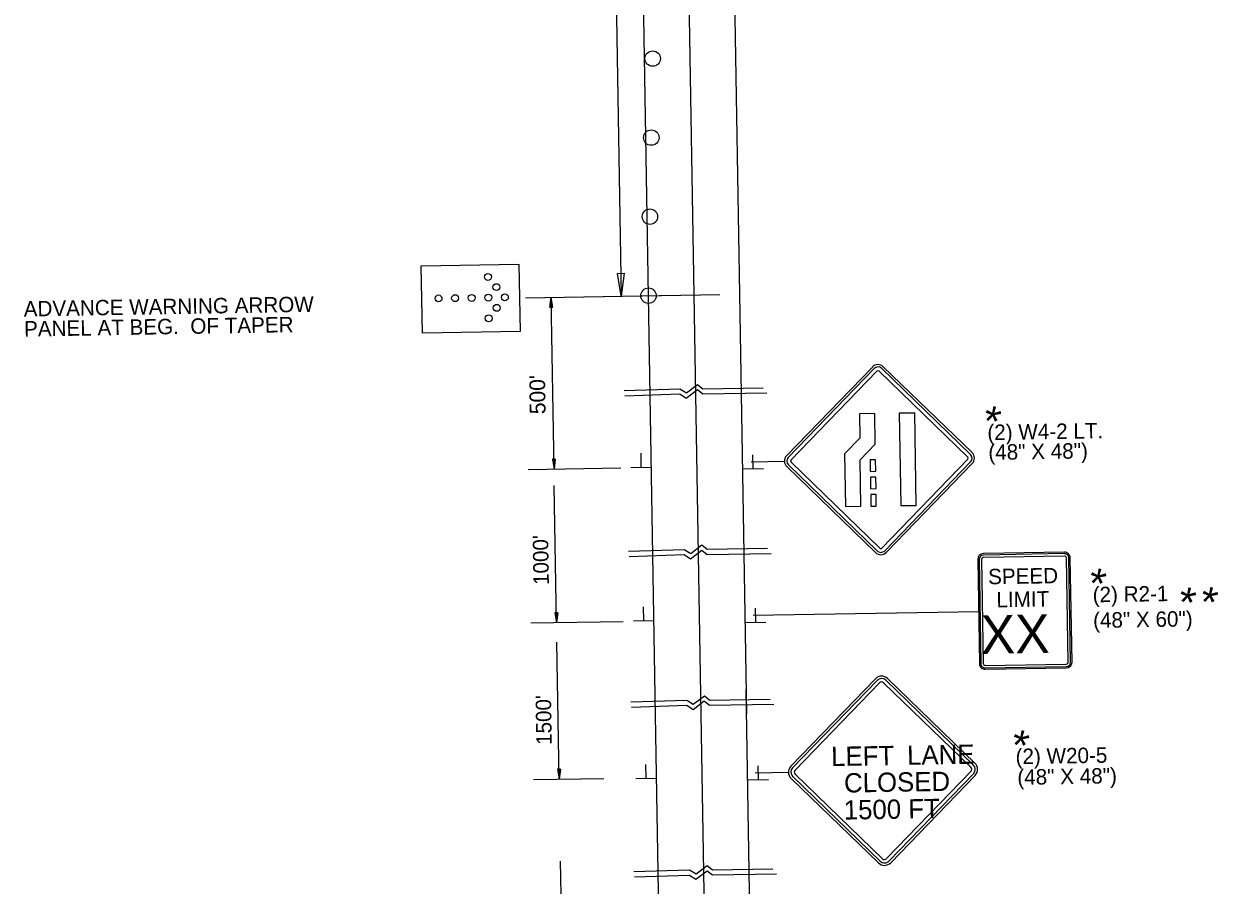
# Model space of a CAD drawing. Extents: x 1676639 to 1677883, y 226447 to 231777.
# Drawn here: x 1676959.3 to 1677423.6, y 226975 to 227309.8 of the extents above; entities that cross this region are included whole.
import ezdxf

# ---------------------------------------------------------------- set-up
doc = ezdxf.new("R2010")
doc.units = 0
for name, color, linetype in [('Default', 7, 'Continuous'), ('P_TC_Signs_Permanent', 7, 'Continuous'), ('P_TC_Signs_Temporary', 7, 'Continuous'), ('R_Annotation', 7, 'Continuous')]:
    doc.layers.add(name, color=color, linetype=linetype)

msp = doc.modelspace()

# ---------------------------------------------------------------- linework, layer by layer
at = {"layer": 'Default'}
for p, q in [((1677202.18, 227204.12), (1677190.13, 227931.05)), ((1677219.91, 227204.42), (1677207.86, 227931.34)), ((1677237.64, 227204.71), (1677225.59, 227931.64)), ((1677183.93, 227664.92), (1677191.58, 227203.95)), ((1677190.1, 227212.79), (1677192.76, 227212.83)), ((1677191.58, 227203.95), (1677190.1, 227212.79)), ((1677192.76, 227212.83), (1677191.58, 227203.95)), ((1677154.34, 227203.33), (1677229.96, 227204.58)), ((1677163.82, 227199.66), (1677164.33, 227203.49)), ((1677163.92, 227199.66), (1677164.34, 227202.86)), ((1677164.01, 227199.66), (1677164.35, 227202.2)), ((1677165.44, 227136.72), (1677164.33, 227203.49)), ((1677164.97, 227199.68), (1677164.33, 227203.49)), ((1677164.87, 227199.68), (1677164.34, 227202.86)), ((1677164.77, 227199.68), (1677164.35, 227202.2)), ((1677177.62, 227203.71), (1677213.53, 227204.31)), ((1677204.89, 227041.03), (1677202.18, 227204.12)), ((1677222.62, 227041.32), (1677219.91, 227204.42)), ((1677240.35, 227041.62), (1677237.64, 227204.71)), ((1677163.82, 227199.66), (1677164.97, 227199.68)), ((1677164.11, 227199.66), (1677164.36, 227201.56)), ((1677164.21, 227199.67), (1677164.37, 227200.91)), ((1677164.3, 227199.67), (1677164.38, 227200.27)), ((1677164.68, 227199.67), (1677164.36, 227201.56)), ((1677164.58, 227199.67), (1677164.37, 227200.91)), ((1677164.48, 227199.67), (1677164.38, 227200.27)), ((1677199.36, 227137.4), (1677199.27, 227142.85)), ((1677242.88, 227136.83), (1677242.79, 227142.28)), ((1677155.45, 227136.56), (1677191.36, 227137.15)), ((1677165.95, 227140.56), (1677164.8, 227140.54)), ((1677164.8, 227140.54), (1677165.44, 227136.72)), ((1677164.9, 227140.54), (1677165.43, 227137.36)), ((1677164.99, 227140.54), (1677165.42, 227138.02)), ((1677165.09, 227140.54), (1677165.4, 227138.66)), ((1677165.19, 227140.54), (1677165.39, 227139.3)), ((1677165.28, 227140.55), (1677165.38, 227139.94)), ((1677165.46, 227140.55), (1677165.38, 227139.94)), ((1677165.56, 227140.55), (1677165.39, 227139.3)), ((1677165.66, 227140.55), (1677165.4, 227138.66)), ((1677165.75, 227140.55), (1677165.42, 227138.02)), ((1677165.85, 227140.55), (1677165.43, 227137.36)), ((1677165.95, 227140.56), (1677165.44, 227136.72)), ((1677203.33, 227137.35), (1677195.35, 227137.22)), ((1677246.85, 227136.78), (1677238.87, 227136.65)), ((1677166.43, 227077.05), (1677165.54, 227130.27)), ((1677200.35, 227077.73), (1677200.26, 227083.17)), ((1677243.87, 227077.16), (1677243.78, 227082.61)), ((1677156.44, 227076.88), (1677192.35, 227077.48)), ((1677166.94, 227080.88), (1677165.79, 227080.86)), ((1677165.79, 227080.86), (1677166.43, 227077.05)), ((1677165.88, 227080.87), (1677166.42, 227077.69)), ((1677165.98, 227080.87), (1677166.4, 227078.35)), ((1677166.08, 227080.87), (1677166.39, 227078.98)), ((1677166.18, 227080.87), (1677166.38, 227079.63)), ((1677166.27, 227080.87), (1677166.37, 227080.27)), ((1677166.45, 227080.87), (1677166.37, 227080.27)), ((1677166.55, 227080.88), (1677166.38, 227079.63)), ((1677166.65, 227080.88), (1677166.39, 227078.98)), ((1677166.74, 227080.88), (1677166.4, 227078.35)), ((1677166.84, 227080.88), (1677166.42, 227077.69)), ((1677166.94, 227080.88), (1677166.43, 227077.05)), ((1677204.32, 227077.68), (1677196.34, 227077.54)), ((1677247.84, 227077.11), (1677239.86, 227076.98)), ((1677167.44, 227016.17), (1677166.55, 227069.4)), ((1677241.81, 226953.29), (1677240.19, 227050.97)), ((1677206.35, 226952.71), (1677204.89, 227041.03)), ((1677224.08, 226953), (1677222.62, 227041.32)), ((1677201.24, 227016.46), (1677201.15, 227021.91)), ((1677244.88, 227015.9), (1677244.79, 227021.34)), ((1677157.45, 227016.01), (1677184.83, 227016.46)), ((1677167.95, 227020.01), (1677166.8, 227019.99)), ((1677166.8, 227019.99), (1677167.44, 227016.17)), ((1677166.89, 227019.99), (1677167.42, 227016.81)), ((1677166.99, 227019.99), (1677167.41, 227017.47)), ((1677167.09, 227019.99), (1677167.4, 227018.11)), ((1677167.18, 227019.99), (1677167.39, 227018.75)), ((1677167.28, 227020), (1677167.38, 227019.39)), ((1677167.46, 227020), (1677167.38, 227019.39)), ((1677167.56, 227020), (1677167.39, 227018.75)), ((1677167.66, 227020), (1677167.4, 227018.11)), ((1677167.75, 227020), (1677167.41, 227017.47)), ((1677167.85, 227020.01), (1677167.42, 227016.81)), ((1677167.95, 227020.01), (1677167.44, 227016.17)), ((1677205.21, 227016.41), (1677197.23, 227016.28)), ((1677248.85, 227015.84), (1677240.88, 227015.71)), ((1677168.85, 226930.99), (1677167.97, 226984.21))]:
    msp.add_line(p, q, dxfattribs=at)
msp.add_lwpolyline([(1677152.25, 227190.14), (1677114.27, 227189.51), (1677113.83, 227215.78), (1677151.81, 227216.41)], close=True, dxfattribs=at)
for points in [[(1677192.7, 227167.26), (1677214.42, 227167.95), (1677216.92, 227166.34), (1677221.28, 227169.64), (1677223.34, 227167.97), (1677246.77, 227168.36)], [(1677192.93, 227165.23), (1677214.37, 227165.92), (1677216.86, 227164.3), (1677221.22, 227167.6), (1677223.29, 227165.94), (1677248.23, 227166.34)], [(1677194.38, 227104.81), (1677216.1, 227105.5), (1677218.59, 227103.89), (1677222.96, 227107.19), (1677225.02, 227105.52), (1677248.45, 227105.91)], [(1677194.61, 227102.78), (1677216.05, 227103.46), (1677218.54, 227101.85), (1677222.9, 227105.15), (1677224.97, 227103.48), (1677249.91, 227103.89)], [(1677195.35, 227046.21), (1677217.08, 227046.9), (1677219.57, 227045.29), (1677223.93, 227048.59), (1677225.99, 227046.92), (1677249.42, 227047.31)], [(1677195.58, 227044.18), (1677217.02, 227044.87), (1677219.51, 227043.25), (1677223.88, 227046.55), (1677225.94, 227044.89), (1677250.88, 227045.29)], [(1677196.44, 226980.22), (1677218.17, 226980.91), (1677220.66, 226979.3), (1677225.02, 226982.6), (1677227.09, 226980.94), (1677250.51, 226981.32)], [(1677196.67, 226978.19), (1677218.12, 226978.88), (1677220.61, 226977.26), (1677224.97, 226980.56), (1677227.04, 226978.9), (1677251.98, 226979.3)]]:
    msp.add_lwpolyline(points, dxfattribs=at)
for centre, radius in [((1677203.8, 227296.31), 3), ((1677203.26, 227265.58), 3), ((1677202.72, 227234.85), 3), ((1677139.75, 227211.42), 1.34), ((1677143.04, 227207.45), 1.34), ((1677202.18, 227204.12), 3), ((1677120.53, 227203.05), 1.34), ((1677126.98, 227203.16), 1.34), ((1677133.43, 227203.26), 1.34), ((1677139.88, 227203.37), 1.34), ((1677146.33, 227203.48), 1.34), ((1677143.17, 227199.4), 1.34), ((1677140.02, 227195.32), 1.34)]:
    msp.add_circle(centre, radius, dxfattribs=at)
at = {"layer": 'P_TC_Signs_Permanent'}
for p, q in [((1677289.22, 227176.39), (1677255.85, 227141.89)), ((1677299.68, 227158.5), (1677305.68, 227158.6)), ((1677255.92, 227137.65), (1677290.42, 227104.28)), ((1677294.66, 227104.35), (1677328.04, 227138.85)), ((1677330.18, 227101.57), (1677330.85, 227061.08)), ((1677330.74, 227101.58), (1677331.41, 227061.08)), ((1677331.67, 227101.59), (1677332.35, 227061.1)), ((1677363.88, 227104.38), (1677332.39, 227103.86)), ((1677363.89, 227103.82), (1677332.4, 227103.29)), ((1677363.91, 227102.88), (1677332.41, 227102.36)), ((1677365.34, 227061.65), (1677364.67, 227102.14)), ((1677366.28, 227061.66), (1677365.61, 227102.16)), ((1677366.84, 227061.67), (1677366.17, 227102.17)), ((1677333.11, 227060.36), (1677364.6, 227060.88)), ((1677333.12, 227059.43), (1677364.62, 227059.95)), ((1677333.13, 227058.86), (1677364.63, 227059.38))]:
    msp.add_line(p, q, dxfattribs=at)
for points in [[(1677256.5, 227141.27), (1677289.87, 227175.77)], [(1677290.95, 227174.72), (1677257.58, 227140.23)], [(1677326.3, 227141.37), (1677291.8, 227174.74)], [(1677292.84, 227175.82), (1677327.34, 227142.44)], [(1677327.97, 227143.09), (1677310.72, 227159.78), (1677293.47, 227176.46)], [(1677291.05, 227104.93), (1677256.55, 227138.3)], [(1677257.59, 227139.38), (1677292.09, 227106)], [(1677292.94, 227106.02), (1677326.31, 227140.52)], [(1677327.39, 227139.47), (1677294.01, 227104.97)]]:
    msp.add_lwpolyline(points, dxfattribs=at)
for points in [[(1677278.74, 227122.15), (1677284.74, 227122.25), (1677284.44, 227140.25), (1677290.34, 227146.35), (1677290.14, 227158.34), (1677284.15, 227158.24), (1677284.3, 227148.73), (1677278.4, 227142.63)], [(1677300.28, 227122.51), (1677306.28, 227122.61), (1677305.68, 227158.6), (1677299.68, 227158.5)], [(1677288.42, 227135.81), (1677290.52, 227135.85), (1677290.44, 227140.35), (1677288.34, 227140.31)], [(1677288.53, 227129.06), (1677290.63, 227129.1), (1677290.56, 227133.6), (1677288.46, 227133.56)], [(1677288.64, 227122.31), (1677290.74, 227122.35), (1677290.67, 227126.85), (1677288.57, 227126.81)]]:
    msp.add_lwpolyline(points, close=True, dxfattribs=at)
for centre, radius, start, end in [((1677291.38, 227174.31), 3, 45.9497, 135.9497), ((1677291.38, 227174.31), 2.1, 45.9497, 135.9497), ((1677291.38, 227174.31), 0.6, 45.9497, 135.9497), ((1677258.01, 227139.81), 3, 135.9497, 225.9497), ((1677325.88, 227140.93), 2.1, 315.9497, 45.9497), ((1677325.88, 227140.93), 3, 315.9497, 45.9497), ((1677258.01, 227139.81), 2.1, 135.9497, 225.9497), ((1677258.01, 227139.81), 0.6, 135.9497, 225.9497), ((1677325.88, 227140.93), 0.6, 315.9497, 45.9497), ((1677292.51, 227106.43), 2.1, 225.9497, 315.9497), ((1677292.51, 227106.43), 0.6, 225.9497, 315.9497), ((1677292.51, 227106.43), 3, 225.9497, 315.9497), ((1677332.42, 227101.61), 2.25, 90.9497, 180.9497), ((1677332.42, 227101.61), 1.69, 90.9497, 180.9497), ((1677332.42, 227101.61), 0.75, 90.9497, 180.9497), ((1677363.92, 227102.13), 2.25, 0.9497, 90.9497), ((1677363.92, 227102.13), 1.69, 0.9497, 90.9497), ((1677363.92, 227102.13), 0.75, 0.9497, 90.9497), ((1677333.1, 227061.11), 2.25, 180.9497, 270.9497), ((1677333.1, 227061.11), 1.69, 180.9497, 270.9497), ((1677333.1, 227061.11), 0.75, 180.9497, 270.9497), ((1677364.59, 227061.63), 0.75, 270.9497, 0.9497), ((1677364.59, 227061.63), 1.69, 270.9497, 0.9497), ((1677364.59, 227061.63), 2.25, 270.9497, 0.9497)]:
    msp.add_arc(centre, radius, start, end, dxfattribs=at)
at = {"layer": 'P_TC_Signs_Temporary'}
for p, q in [((1677257.53, 227021.22), (1677290.38, 227055.18)), ((1677258.2, 227020.56), (1677291.06, 227054.52)), ((1677259.15, 227019.65), (1677292, 227053.61)), ((1677293.59, 227053.64), (1677327.55, 227020.79)), ((1677294.5, 227054.58), (1677328.46, 227021.73)), ((1677295.15, 227055.26), (1677329.11, 227022.4)), ((1677291.57, 226983.59), (1677257.61, 227016.44)), ((1677292.22, 226984.27), (1677258.26, 227017.12)), ((1677293.13, 226985.21), (1677259.17, 227018.06)), ((1677327.58, 227019.2), (1677294.72, 226985.24)), ((1677328.52, 227018.28), (1677295.67, 226984.32)), ((1677329.19, 227017.63), (1677296.34, 226983.67))]:
    msp.add_line(p, q, dxfattribs=at)
for centre, radius, start, end in [((1677292.81, 227052.83), 3.38, 45.9497, 135.9497), ((1677292.81, 227052.83), 2.44, 45.9497, 135.9497), ((1677292.81, 227052.83), 1.13, 45.9497, 135.9497), ((1677259.96, 227018.87), 3.38, 135.9497, 225.9497), ((1677326.77, 227019.98), 2.44, 315.9497, 45.9497), ((1677326.77, 227019.98), 3.38, 315.9497, 45.9497), ((1677259.96, 227018.87), 2.44, 135.9497, 225.9497), ((1677259.96, 227018.87), 1.12, 135.9497, 225.9497), ((1677326.77, 227019.98), 1.12, 315.9497, 45.9497), ((1677293.92, 226986.02), 2.44, 225.9497, 315.9497), ((1677293.92, 226986.02), 1.13, 225.9497, 315.9497), ((1677293.92, 226986.02), 3.38, 225.9497, 315.9497)]:
    msp.add_arc(centre, radius, start, end, dxfattribs=at)
at = {"layer": 'R_Annotation'}
for p, q in [((1677242.08, 227139.54), (1677255.01, 227139.76)), ((1677242.85, 227079.87), (1677330.51, 227081.32)), ((1677243.65, 227018.6), (1677256.58, 227018.81))]:
    msp.add_line(p, q, dxfattribs=at)

# ---------------------------------------------------------------- texts
at = {"layer": 'Default'}
for s, height, p in [("500'", 6.12, (1677162.17, 227158.09)), ("1000'", 6, (1677163.46, 227091.69)), ("1500'", 6, (1677164.58, 227029.5))]:
    msp.add_text(s, height=height, rotation=90.9497, dxfattribs=at).set_placement(p)
at = {"layer": 'P_TC_Signs_Permanent'}
for s, height, p in [('SPEED', 6, (1677334.27, 227091.89)), ('LIMIT', 6, (1677337.5, 227082.94)), ('XX', 15, (1677331.48, 227064.84))]:
    msp.add_text(s, height=height, rotation=0.9497, dxfattribs=at).set_placement(p)
at = {"layer": 'P_TC_Signs_Temporary'}
for s, p in [('LEFT\u2002LANE', (1677273.24, 227021.22)), ('CLOSED', (1677278.25, 227010.92)), ('1500 FT', (1677278.15, 227000.42))]:
    msp.add_text(s, height=7.5, rotation=0.9497, dxfattribs=at).set_placement(p)
at = {"layer": 'R_Annotation'}
for s, height, rotation, p in [('ADVANCE WARNING ARROW', 6, 0.9497, (1676959.3, 227195.99)), ('PANEL AT BEG.  OF TAPER', 6, 0.9497, (1676959.43, 227188.2)), ('*', 12, 135.9497, (1677344.51, 227162.18)), ('(2) W4-2 LT.', 6, 0.9497, (1677333.98, 227147.96)), ('(48" X 48")', 6, 0.9497, (1677334.36, 227140.24)), ('*', 12, 135.9497, (1677385.45, 227099.11)), ('(2) R2-1', 6, 0.9497, (1677374.93, 227084.89)), ('*', 12, 135.9497, (1677420.34, 227091.73)), ('*', 12, 135.9497, (1677428.87, 227091.87)), ('(48" X 60")', 6, 0.9497, (1677375.09, 227074.92)), ('*', 12, 135.9497, (1677355.49, 227036.17)), ('(2) W20-5', 6, 0.9497, (1677344.96, 227021.96)), ('(48" X 48")', 6, 0.9497, (1677345.64, 227013.91))]:
    msp.add_text(s, height=height, rotation=rotation, dxfattribs=at).set_placement(p)

doc.saveas('drawing.dxf')
